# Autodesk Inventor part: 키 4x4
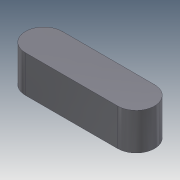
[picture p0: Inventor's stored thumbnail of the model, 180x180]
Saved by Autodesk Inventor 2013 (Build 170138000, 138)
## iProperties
Company: 한국ATC센터
Created: 2014-10
Part Number: 키 4x4
Document SubType Name: Modeling
Designer: KYOUNG IL JANG
Density: 1 g/cm^3
Mass: 0.210265 g
Surface Area: 2.35398 cm^2
Volume: 0.210265 cm^3
Material: 일반
Author: KYOUNG IL JANG
Revision Number: 1
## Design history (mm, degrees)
sketch "스케치1"
  geometry: L1 (-5, -2)-(5, -2); L2 (5, 2)-(-5, 2); A1 r 2 centre (5, 0) between (5, -2) and (5, 2); A2 r 2 centre (-5, 0) between (-5, 2) and (-5, -2); 2 further points
  constraints: 4 end point, 4 point on circle, 4 tangent, 2 centre point, 1 horizontal, 1 horizontal alignment, 1 midpoint, 1 parallel, 1 vertical alignment
  dimensions: "d0" = 4 distance between parallel lines of L1 L2; "d1" = 14 dimension on A1 A2
extrude "돌출1" new body sketch "스케치1" stored distance "d2" = 4; taper "d3" = 0 deg
node "솔리드1"
